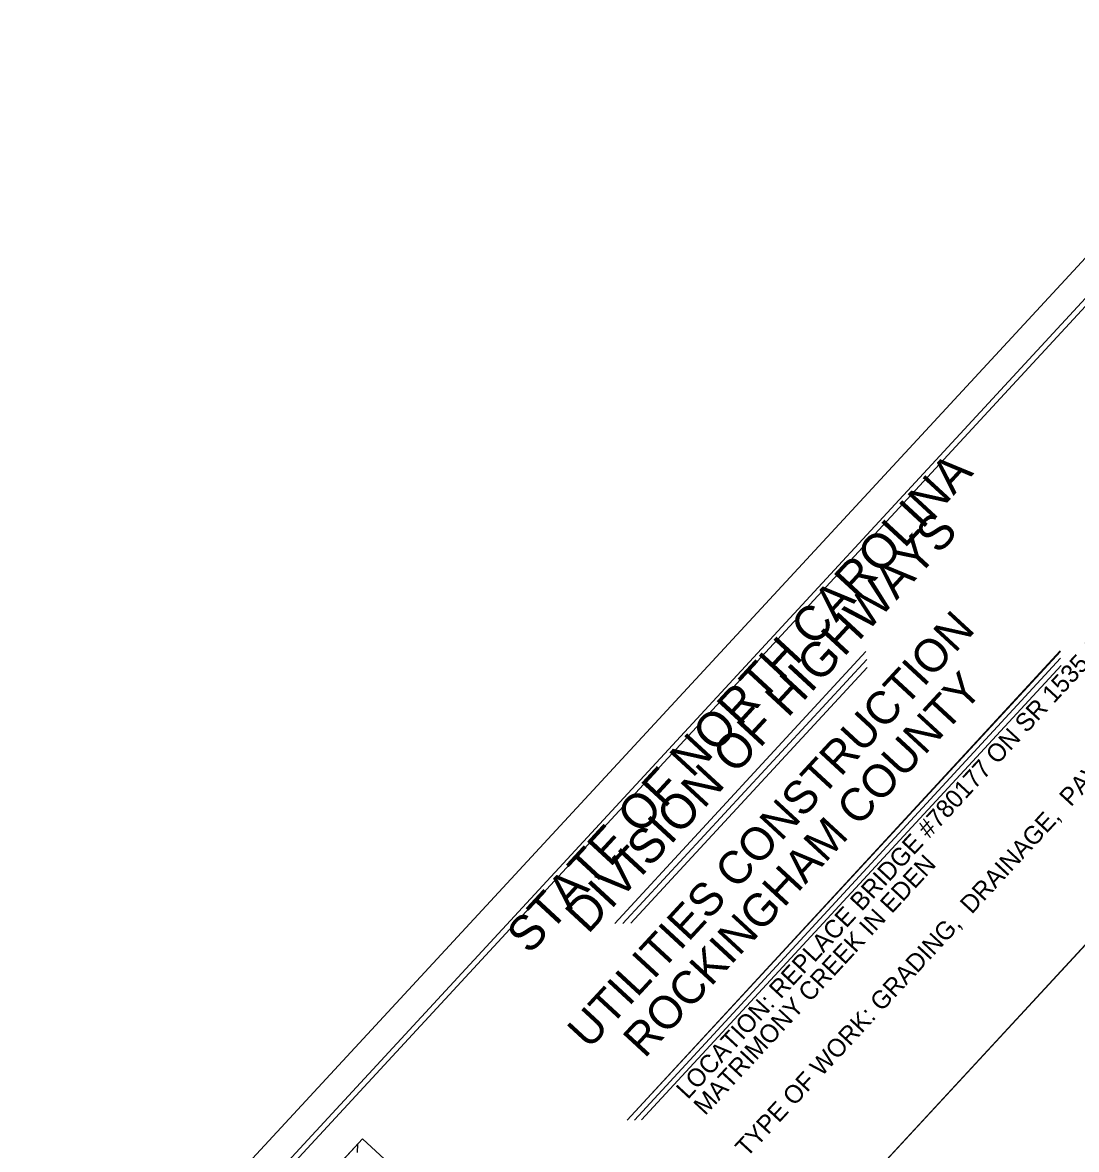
# Model space of a CAD drawing. Extents: x 1766669 to 1770980, y 998119 to 1002502.
# Drawn here: x 1766669 to 1768756, y 1000271 to 1002502 of the extents above; entities that cross this region are included whole.
import ezdxf

# ---------------------------------------------------------------- set-up
doc = ezdxf.new("R2010")
doc.units = 0
for name, color, linetype in [('Default', 7, 'Continuous'), ('Default Symbol CELL', 7, 'Continuous'), ('Exist Roads EOT', 7, 'Continuous'), ('Exist Survey Setup Group', 7, 'Continuous'), ('PH Exist DTM Breakline', 7, 'Continuous')]:
    doc.layers.add(name, color=color, linetype=linetype)

msp = doc.modelspace()

# ---------------------------------------------------------------- linework, layer by layer
at = {"layer": 'Default'}
msp.add_lwpolyline([(1766911.4, 999825.8), (1767342.4, 1000292), (1767769.6, 999897.2), (1767338.6, 999431)], close=True, dxfattribs=at)
at = {"layer": 'Default Symbol CELL'}
for p, q in [((1769179.9, 1002395.5), (1766757.7, 999775.1)), ((1769180.5, 1002379.9), (1766847.8, 999856.4)), ((1767842.2, 1000718), (1768339.4, 1001256.7)), ((1767866.4, 1000328.9), (1768724, 1001257.7)), ((1767866.4, 1000328.9), (1768724.5, 1001256.9)), ((1767857.9, 1000718.2), (1768341.1, 1001240.7)), ((1767880.7, 1000328.9), (1768724.9, 1001243.4)), ((1767894.6, 1000329.4), (1768726.4, 1001228.7)), ((1767873.5, 1000718.4), (1768341.8, 1001225.1)), ((1766911.4, 999825.8), (1767342.4, 1000292)), ((1767342.4, 1000292), (1767826.5, 999844.5))]:
    msp.add_line(p, q, dxfattribs=at)
at = {"layer": 'Exist Roads EOT'}
msp.add_line((1767332.4, 1000281.2), (1767331.3, 1000264.5), dxfattribs=at)
at = {"layer": 'Exist Survey Setup Group'}
for points in [[(1768011.1, 999850.8), (1769408.2, 1001362.3), (1770013.2, 1000803.1), (1768616, 999291.6)], [(1768011.1, 999850.8), (1769409.4, 1001362), (1770014.3, 1000802.4), (1768615.9, 999291.1)]]:
    msp.add_lwpolyline(points, close=True, dxfattribs=at)
at = {"layer": 'PH Exist DTM Breakline'}
msp.add_lwpolyline([(1766668.6, 999760.2), (1769205.6, 1002501.9), (1770979.8, 1000860.3), (1768442.7, 998118.5)], close=True, dxfattribs=at)

# ---------------------------------------------------------------- texts
at = {"layer": 'Default Symbol CELL'}
for s, height, rotation, p in [('STATE OF NORTH CAROLINA', 68.859, 47.2797, (1767672.8, 1000654.9)), ('LOCATION: REPLACE BRIDGE #780177 ON SR 1535 (PRICE RD) OVER', 35.736, 47.237, (1767986.5, 1000368.3)), ('DIVISION OF HIGHWAYS', 68.859, 47.2797, (1767788.8, 1000695.4)), ('TYPE OF WORK: GRADING,  DRAINAGE,  PAVING, & STRUCTURE ', 35.736, 47.237, (1768103.6, 1000253.6)), ('UTILITIES CONSTRUCTION', 65.069, 47.2797, (1767790.8, 1000467.1)), ('ROCKINGHAM COUNTY ', 65.069, 47.2797, (1767901, 1000449.6)), ('MATRIMONY CREEK IN EDEN ', 35.736, 47.237, (1768020.9, 1000336.5))]:
    msp.add_text(s, height=height, rotation=rotation, dxfattribs=at).set_placement(p)

doc.saveas('drawing.dxf')
